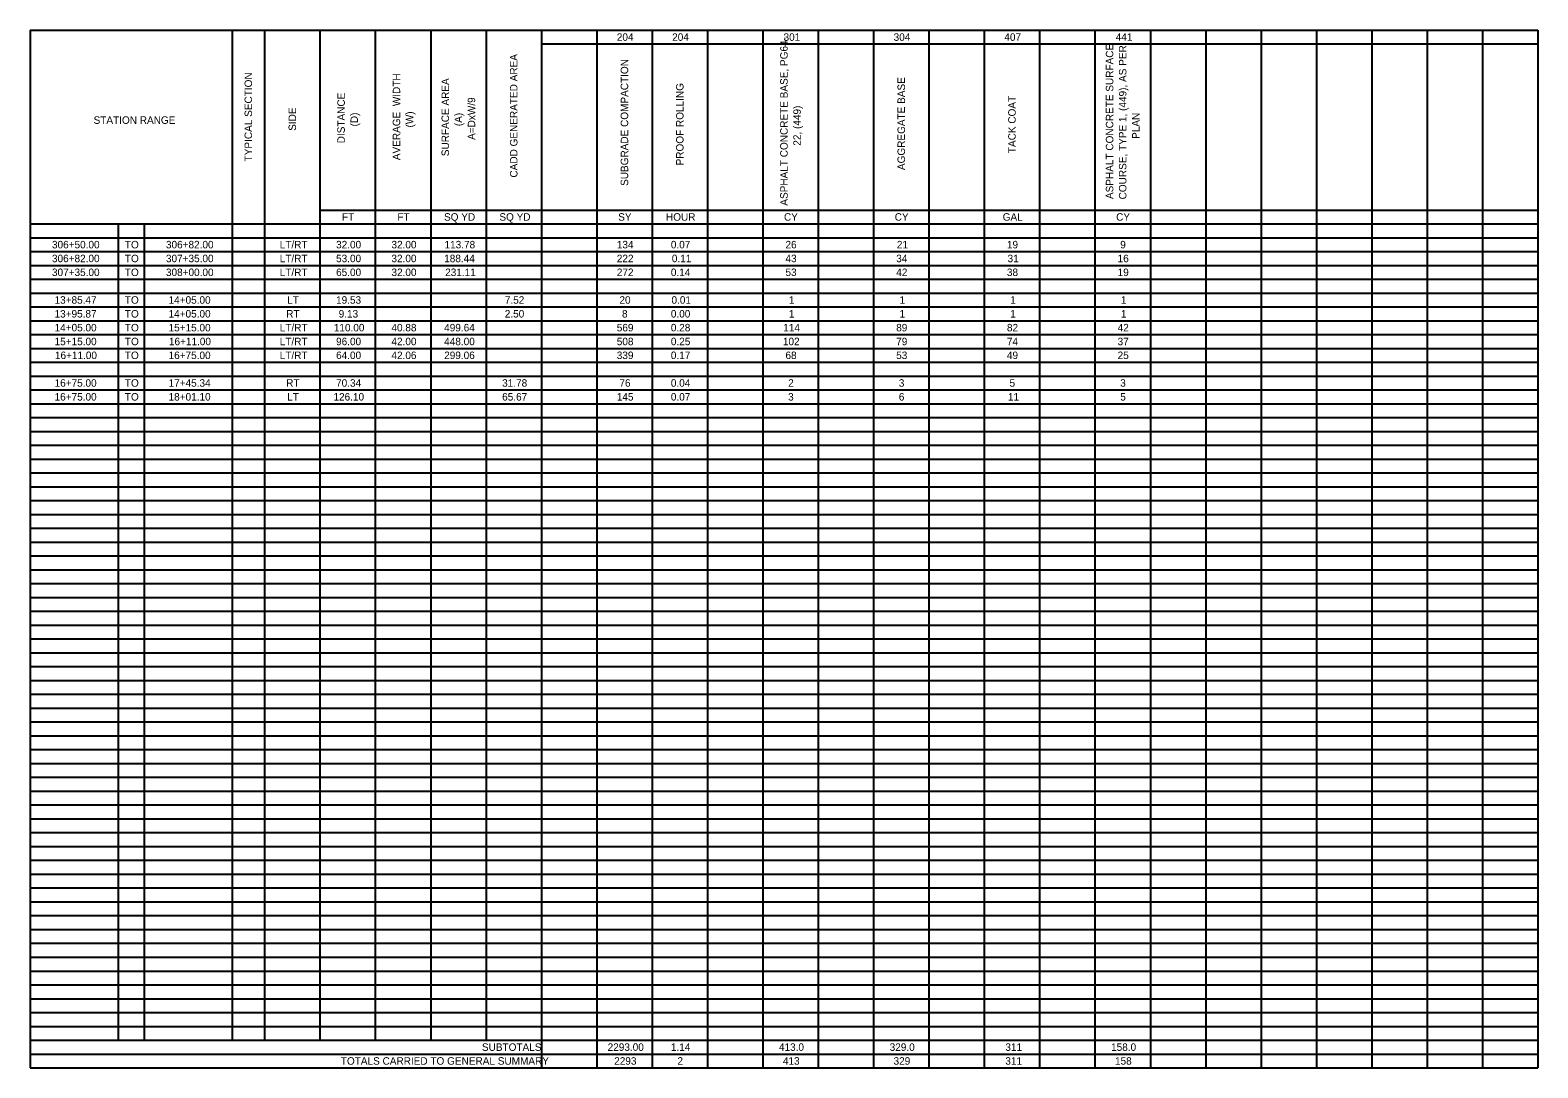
# Model space of a CAD drawing. Extents: x -43.4 to 36.7, y 0 to 22.
# Drawn here: x -43.4 to -12.89, y 0.48 to 21.48 of the extents above; entities that cross this region are included whole.
import ezdxf

# ---------------------------------------------------------------- set-up
doc = ezdxf.new("R2010")
doc.units = 0
doc.layers.add('Default', color=7, linetype='Continuous')

msp = doc.modelspace()

# ---------------------------------------------------------------- linework, layer by layer
at = {"layer": 'Default'}
for p, q in [((-43.398, 21.475), (-12.895, 21.475)), ((-43.398, 21.475), (-43.398, 0.475)), ((-39.314, 21.475), (-39.314, 1.035)), ((-38.655, 21.475), (-38.655, 1.035)), ((-37.535, 21.475), (-37.535, 1.035)), ((-36.415, 21.475), (-36.415, 1.035)), ((-35.295, 21.475), (-35.295, 1.035)), ((-34.175, 21.475), (-34.175, 1.035)), ((-33.055, 21.475), (-33.055, 0.475)), ((-31.935, 21.475), (-31.935, 0.475)), ((-30.815, 21.475), (-30.815, 0.475)), ((-29.695, 21.475), (-29.695, 0.475)), ((-28.575, 21.475), (-28.575, 0.475)), ((-27.455, 21.475), (-27.455, 0.475)), ((-26.335, 21.475), (-26.335, 0.475)), ((-25.215, 21.475), (-25.215, 0.475)), ((-24.095, 21.475), (-24.095, 0.475)), ((-22.975, 21.475), (-22.975, 0.475)), ((-21.855, 21.475), (-21.855, 0.475)), ((-20.735, 21.475), (-20.735, 0.475)), ((-19.615, 21.475), (-19.615, 0.475)), ((-18.495, 21.475), (-18.495, 0.475)), ((-17.375, 21.475), (-17.375, 0.475)), ((-16.255, 21.475), (-16.255, 0.475)), ((-15.135, 21.475), (-15.135, 0.475)), ((-14.015, 21.475), (-14.015, 0.475)), ((-12.895, 21.475), (-12.895, 0.475)), ((-33.055, 21.195), (-12.895, 21.195)), ((-37.535, 17.835), (-12.895, 17.835)), ((-43.398, 17.555), (-12.895, 17.555)), ((-41.62, 17.555), (-41.62, 1.035)), ((-41.093, 17.555), (-41.093, 1.035)), ((-43.398, 17.275), (-12.895, 17.275)), ((-43.398, 16.995), (-12.895, 16.995)), ((-43.398, 16.715), (-12.895, 16.715)), ((-43.398, 16.435), (-12.895, 16.435)), ((-43.398, 16.155), (-12.895, 16.155)), ((-43.398, 15.875), (-12.895, 15.875)), ((-43.398, 15.595), (-12.895, 15.595)), ((-43.398, 15.315), (-12.895, 15.315)), ((-43.398, 15.035), (-12.895, 15.035)), ((-43.398, 14.755), (-12.895, 14.755)), ((-43.398, 14.475), (-12.895, 14.475)), ((-43.398, 14.195), (-12.895, 14.195)), ((-43.398, 13.915), (-12.895, 13.915)), ((-43.398, 13.635), (-12.895, 13.635)), ((-43.398, 13.355), (-12.895, 13.355)), ((-43.398, 13.075), (-12.895, 13.075)), ((-43.398, 12.795), (-12.895, 12.795)), ((-43.398, 12.515), (-12.895, 12.515)), ((-43.398, 12.235), (-12.895, 12.235)), ((-43.398, 11.955), (-12.895, 11.955)), ((-43.398, 11.675), (-12.895, 11.675)), ((-43.398, 11.395), (-12.895, 11.395)), ((-43.398, 11.115), (-12.895, 11.115)), ((-43.398, 10.835), (-12.895, 10.835)), ((-43.398, 10.555), (-12.895, 10.555)), ((-43.398, 10.275), (-12.895, 10.275)), ((-43.398, 9.995), (-12.895, 9.995)), ((-43.398, 9.715), (-12.895, 9.715)), ((-43.398, 9.435), (-12.895, 9.435)), ((-43.398, 9.155), (-12.895, 9.155)), ((-43.398, 8.875), (-12.895, 8.875)), ((-43.398, 8.595), (-12.895, 8.595)), ((-43.398, 8.315), (-12.895, 8.315)), ((-43.398, 8.035), (-12.895, 8.035)), ((-43.398, 7.755), (-12.895, 7.755)), ((-43.398, 7.475), (-12.895, 7.475)), ((-43.398, 7.195), (-12.895, 7.195)), ((-43.398, 6.915), (-12.895, 6.915)), ((-43.398, 6.635), (-12.895, 6.635)), ((-43.398, 6.355), (-12.895, 6.355)), ((-43.398, 6.075), (-12.895, 6.075)), ((-43.398, 5.795), (-12.895, 5.795)), ((-43.398, 5.515), (-12.895, 5.515)), ((-43.398, 5.235), (-12.895, 5.235)), ((-43.398, 4.955), (-12.895, 4.955)), ((-43.398, 4.675), (-12.895, 4.675)), ((-43.398, 4.395), (-12.895, 4.395)), ((-43.398, 4.115), (-12.895, 4.115)), ((-43.398, 3.835), (-12.895, 3.835)), ((-43.398, 3.555), (-12.895, 3.555)), ((-43.398, 3.275), (-12.895, 3.275)), ((-43.398, 2.995), (-12.895, 2.995)), ((-43.398, 2.715), (-12.895, 2.715)), ((-43.398, 2.435), (-12.895, 2.435)), ((-43.398, 2.155), (-12.895, 2.155)), ((-43.398, 1.875), (-12.895, 1.875)), ((-43.398, 1.595), (-12.895, 1.595)), ((-43.398, 1.315), (-12.895, 1.315)), ((-43.398, 1.035), (-12.895, 1.035)), ((-43.398, 0.755), (-12.895, 0.755)), ((-43.398, 0.475), (-12.895, 0.475))]:
    msp.add_line(p, q, dxfattribs=at)

# ---------------------------------------------------------------- texts
for s, height, p in [('204', 0.1515, (-31.529, 21.259)), ('204', 0.1515, (-30.409, 21.259)), ('301', 0.1515, (-28.156, 21.259)), ('304', 0.1515, (-25.929, 21.259)), ('407', 0.1515, (-23.689, 21.259)), ('441', 0.1515, (-21.436, 21.259)), ('STATION RANGE', 0.15153, (-42.115, 19.579)), ('FT', 0.1515, (-37.089, 17.619)), ('FT', 0.1515, (-35.969, 17.619)), ('SQ YD', 0.1515, (-35.025, 17.619)), ('SQ YD', 0.1515, (-33.905, 17.619)), ('SY', 0.1515, (-31.501, 17.619)), ('HOUR', 0.1515, (-30.534, 17.619)), ('CY', 0.1515, (-28.147, 17.619)), ('CY', 0.1515, (-25.907, 17.619)), ('GAL', 0.1515, (-23.722, 17.619)), ('CY', 0.1515, (-21.427, 17.619)), ('306+50.00', 0.1515, (-42.957, 17.059)), ('TO', 0.1515, (-41.482, 17.059)), ('306+82.00', 0.1515, (-40.651, 17.059)), ('LT/RT', 0.1515, (-38.349, 17.059)), ('32.00', 0.1515, (-37.209, 17.059)), ('32.00', 0.1515, (-36.089, 17.059)), ('113.78', 0.1515, (-35.015, 17.059)), ('134', 0.1515, (-31.529, 17.059)), ('0.07', 0.1515, (-30.436, 17.059)), ('26', 0.1515, (-28.117, 17.059)), ('21', 0.1515, (-25.863, 17.059)), ('19', 0.1515, (-23.637, 17.059)), ('9', 0.152, (-21.344, 17.059)), ('306+82.00', 0.1515, (-42.957, 16.779)), ('TO', 0.1515, (-41.482, 16.779)), ('307+35.00', 0.1515, (-40.651, 16.779)), ('LT/RT', 0.1515, (-38.349, 16.779)), ('53.00', 0.1515, (-37.209, 16.779)), ('32.00', 0.1515, (-36.089, 16.779)), ('188.44', 0.1515, (-35.022, 16.779)), ('222', 0.1515, (-31.529, 16.779)), ('0.11', 0.1515, (-30.416, 16.779)), ('43', 0.1515, (-28.117, 16.779)), ('34', 0.1515, (-25.876, 16.779)), ('31', 0.1515, (-23.623, 16.779)), ('16', 0.1515, (-21.397, 16.779)), ('307+35.00', 0.1515, (-42.957, 16.499)), ('TO', 0.1515, (-41.482, 16.499)), ('308+00.00', 0.1515, (-40.651, 16.499)), ('LT/RT', 0.1515, (-38.349, 16.499)), ('65.00', 0.1515, (-37.209, 16.499)), ('32.00', 0.1515, (-36.089, 16.499)), ('231.11', 0.1515, (-35.002, 16.499)), ('272', 0.1515, (-31.529, 16.499)), ('0.14', 0.1515, (-30.436, 16.499)), ('53', 0.1515, (-28.117, 16.499)), ('42', 0.1515, (-25.876, 16.499)), ('38', 0.1515, (-23.637, 16.499)), ('19', 0.1515, (-21.397, 16.499)), ('13+85.47', 0.1515, (-42.905, 15.939)), ('TO', 0.1515, (-41.482, 15.939)), ('14+05.00', 0.1515, (-40.598, 15.939)), ('LT', 0.1515, (-38.197, 15.939)), ('19.53', 0.1515, (-37.209, 15.939)), ('7.52', 0.1515, (-33.795, 15.939)), ('20', 0.1515, (-31.476, 15.939)), ('0.01', 0.1515, (-30.423, 15.939)), ('1', 0.152, (-28.05, 15.939)), ('1', 0.152, (-25.81, 15.939)), ('1', 0.152, (-23.57, 15.939)), ('1', 0.152, (-21.33, 15.939)), ('13+95.87', 0.1515, (-42.905, 15.659)), ('TO', 0.1515, (-41.482, 15.659)), ('14+05.00', 0.1515, (-40.598, 15.659)), ('RT', 0.1515, (-38.218, 15.659)), ('9.13', 0.1515, (-37.156, 15.659)), ('2.50', 0.1515, (-33.796, 15.659)), ('8', 0.152, (-31.424, 15.659)), ('0.00', 0.1515, (-30.436, 15.659)), ('1', 0.152, (-28.05, 15.659)), ('1', 0.152, (-25.81, 15.659)), ('1', 0.152, (-23.57, 15.659)), ('1', 0.152, (-21.33, 15.659)), ('14+05.00', 0.1515, (-42.904, 15.379)), ('15+15.00', 0.1515, (-42.904, 15.099)), ('TO', 0.1515, (-41.482, 15.379)), ('TO', 0.1515, (-41.482, 15.099)), ('15+15.00', 0.1515, (-40.598, 15.379)), ('16+11.00', 0.1515, (-40.591, 15.099)), ('LT/RT', 0.1515, (-38.349, 15.379)), ('LT/RT', 0.1515, (-38.349, 15.099)), ('110.00', 0.1515, (-37.255, 15.379)), ('96.00', 0.1515, (-37.209, 15.099)), ('40.88', 0.1515, (-36.089, 15.379)), ('42.00', 0.1515, (-36.089, 15.099)), ('499.64', 0.1515, (-35.022, 15.379)), ('448.00', 0.1515, (-35.022, 15.099)), ('569', 0.1515, (-31.53, 15.379)), ('508', 0.1515, (-31.53, 15.099)), ('0.25', 0.1515, (-30.436, 15.099)), ('0.28', 0.1515, (-30.436, 15.379)), ('102', 0.1515, (-28.169, 15.099)), ('114', 0.1515, (-28.162, 15.379)), ('89', 0.1515, (-25.877, 15.379)), ('79', 0.1515, (-25.877, 15.099)), ('82', 0.1515, (-23.636, 15.379)), ('42', 0.1515, (-21.396, 15.379)), ('37', 0.1515, (-21.397, 15.099)), ('16+11.00', 0.1515, (-42.897, 14.819)), ('TO', 0.1515, (-41.482, 14.819)), ('16+75.00', 0.1515, (-40.598, 14.819)), ('LT/RT', 0.1515, (-38.349, 14.819)), ('64.00', 0.1515, (-37.209, 14.819)), ('42.06', 0.1515, (-36.089, 14.819)), ('299.06', 0.1515, (-35.022, 14.819)), ('339', 0.1515, (-31.53, 14.819)), ('0.17', 0.1515, (-30.436, 14.819)), ('68', 0.1515, (-28.117, 14.819)), ('53', 0.1515, (-25.877, 14.819)), ('49', 0.1515, (-23.637, 14.819)), ('74', 0.1515, (-23.636, 15.099)), ('25', 0.1515, (-21.397, 14.819)), ('16+75.00', 0.1515, (-42.904, 14.259)), ('TO', 0.1515, (-41.482, 14.259)), ('17+45.34', 0.1515, (-40.598, 14.259)), ('RT', 0.1515, (-38.218, 14.259)), ('70.34', 0.1515, (-37.209, 14.259)), ('31.78', 0.1515, (-33.849, 14.259)), ('76', 0.1515, (-31.477, 14.259)), ('0.04', 0.1515, (-30.436, 14.259)), ('2', 0.152, (-28.063, 14.259)), ('3', 0.152, (-25.824, 14.259)), ('5', 0.152, (-23.584, 14.259)), ('3', 0.152, (-21.344, 14.259)), ('16+75.00', 0.1515, (-42.904, 13.979)), ('TO', 0.1515, (-41.482, 13.979)), ('18+01.10', 0.1515, (-40.598, 13.979)), ('LT', 0.1515, (-38.197, 13.979)), ('126.10', 0.1515, (-37.262, 13.979)), ('65.67', 0.1515, (-33.849, 13.979)), ('145', 0.1515, (-31.53, 13.979)), ('0.07', 0.1515, (-30.436, 13.979)), ('3', 0.152, (-28.064, 13.979)), ('6', 0.152, (-25.824, 13.979)), ('11', 0.1515, (-23.616, 13.979)), ('5', 0.152, (-21.344, 13.979)), ('SUBTOTALS', 0.1515, (-34.258, 0.819)), ('2293.00', 0.1515, (-31.715, 0.819)), ('1.14', 0.1515, (-30.436, 0.819)), ('413.0', 0.1515, (-28.249, 0.819)), ('329.0', 0.1515, (-26.009, 0.819)), ('311', 0.1515, (-23.669, 0.819)), ('158.0', 0.1515, (-21.529, 0.819)), ('TOTALS CARRIED TO GENERAL SUMMARY', 0.15153, (-37.113, 0.539)), ('2293', 0.1515, (-31.582, 0.539)), ('2', 0.152, (-30.303, 0.539)), ('413', 0.1515, (-28.169, 0.539)), ('329', 0.1515, (-25.93, 0.539)), ('311', 0.1515, (-23.669, 0.539)), ('158', 0.1515, (-21.45, 0.539))]:
    msp.add_text(s, height=height, dxfattribs=at).set_placement(p)
for s, height, p in [('ASPHALT CONCRETE BASE, PG64-', 0.15153, (-28.072, 17.923)), ('ASPHALT CONCRETE SURFACE ', 0.15153, (-21.484, 18.057)), ('COURSE, TYPE 1, (449), AS PER ', 0.15153, (-21.219, 18.05)), ('CADD GENERATED AREA', 0.15153, (-33.539, 18.492)), ('SUBGRADE COMPACTION', 0.15153, (-31.299, 18.323)), ('TYPICAL SECTION', 0.15153, (-38.909, 18.819)), ('AVERAGE  WIDTH', 0.15153, (-35.912, 18.844)), ('SURFACE AREA', 0.15153, (-34.924, 18.924)), ('AGGREGATE BASE', 0.15153, (-25.699, 18.643)), ('DISTANCE', 0.1515, (-37.032, 19.185)), ('PROOF ROLLING', 0.15153, (-30.179, 18.738)), ('TACK COAT', 0.1515, (-23.459, 18.986)), ('SIDE', 0.1515, (-38.019, 19.438)), ('A=DxW/9', 0.1515, (-34.394, 19.254)), ('22, (449)', 0.1515, (-27.807, 19.137)), ('(D)', 0.1515, (-36.767, 19.526)), ('(W)', 0.1515, (-35.647, 19.505)), ('(A)', 0.1515, (-34.659, 19.532)), ('PLAN', 0.1515, (-20.954, 19.274))]:
    msp.add_text(s, height=height, rotation=90, dxfattribs=at).set_placement(p)

doc.saveas('drawing.dxf')
